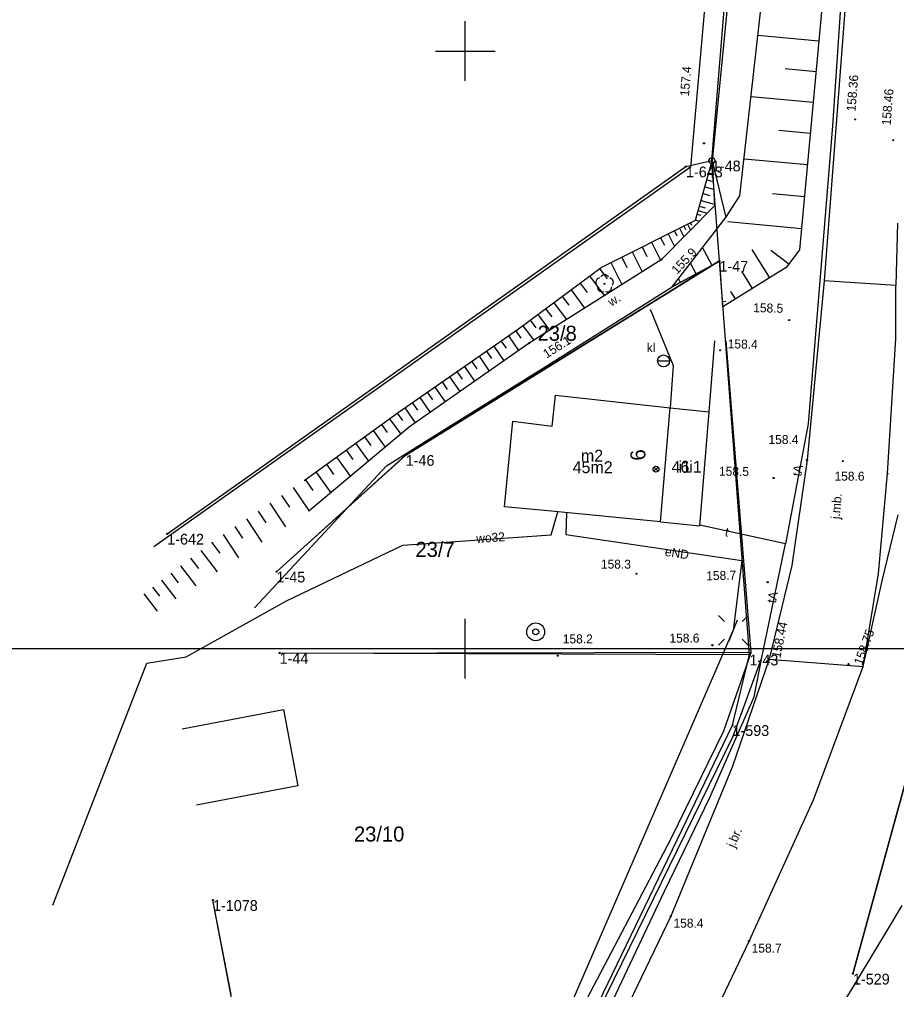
# Model space of a CAD drawing. Extents: x 5598798 to 5599616, y 5661498 to 5662453.
# Drawn here: x 5599112.7 to 5599186.1, y 5661721.5 to 5661802.6 of the extents above; entities that cross this region are included whole.
import ezdxf

# ---------------------------------------------------------------- set-up
doc = ezdxf.new("R2010")
doc.units = 0
for name, color, linetype in [('BUBZ_L_1', 7, 'Continuous'), ('BUIB_L_1', 7, 'Continuous'), ('Dzialki', 7, 'Continuous'), ('EADTD_T_0', 7, 'Continuous'), ('EAPADR_T_0', 7, 'Continuous'), ('EGBB_E_T_0', 7, 'Continuous'), ('EGBB_E_T_1', 7, 'Continuous'), ('EGBB_L_0', 7, 'Continuous'), ('Kontury', 7, 'Continuous'), ('KTJZ_E_T_0', 7, 'Continuous'), ('KTJZ_L_0', 7, 'Continuous'), ('KTOK_L_4', 7, 'Continuous'), ('Numery_dzialek', 7, 'Continuous'), ('Numery_punktow', 7, 'Continuous'), ('OBOP_T_1', 7, 'Continuous'), ('Podzial_sekcyjny_krzyze', 7, 'Continuous'), ('Podzial_sekcyjny_podstawowy', 7, 'Continuous'), ('PTRW_E_T_0', 7, 'Continuous'), ('PTRW_L_1', 7, 'Continuous'), ('Punkty', 7, 'Continuous'), ('RTPW_T_0', 7, 'Continuous'), ('RTPW_T_1', 7, 'Continuous'), ('SUPE_E_T_3', 7, 'Continuous'), ('SUPE_L_3', 7, 'Continuous'), ('SUPT_E_T_0', 7, 'Continuous'), ('SUPT_L_0', 7, 'Continuous'), ('SUPW_E_T_0', 7, 'Continuous'), ('SUPW_L_0', 7, 'Continuous'), ('SUSM_L_4', 7, 'Continuous'), ('SUSM_T_0', 7, 'Continuous'), ('SUUK_E_T_1', 7, 'Continuous'), ('SUUK_T_1', 7, 'Continuous'), ('SUUW_T_1', 7, 'Continuous'), ('Uzytki', 7, 'Continuous')]:
    doc.layers.add(name, color=color, linetype=linetype)

# ---------------------------------------------------------------- blocks, each defined once
blk = doc.blocks.new('GRT')
blk.add_circle((0, 0), 0.25)
blk = doc.blocks.new('GRO')
blk.add_circle((0, 0), 0.045)
blk = doc.blocks.new('1_PADR')
for p, q in [((-0.17675, -0.17675), (0.17675, 0.17675)), ((0.17675, -0.17675), (-0.17675, 0.17675))]:
    blk.add_line(p, q)
blk.add_circle((0, 0), 0.25)
blk = doc.blocks.new('2_OBOP02_01')
blk.add_circle((0, 0), 0.045)
for centre, start, end in [((-0.356659, 0.115892), 102.144465, 221.860023), ((0, 0.375056), 30.140124, 149.859876), ((0.356659, 0.115892), 318.139977, 77.855535), ((-0.220404, -0.303384), 174.148182, 293.854228), ((0.220404, -0.303384), 246.145772, 5.851818)]:
    blk.add_arc(centre, 0.375, start, end)
blk = doc.blocks.new('2_RTPW02')
blk.add_circle((0, 0), 0.045)
blk = doc.blocks.new('2_RTPW01')
blk.add_circle((0, 0), 0.045)
blk = doc.blocks.new('4_SUSM01_01')
for p, q in [((-0.74249, 0.74249), (-1.23746, 1.23746)), ((0.74249, 0.74249), (1.23746, 1.23746)), ((-0.74249, -0.74249), (-1.23746, -1.23746)), ((0.74249, -0.74249), (1.23746, -1.23746))]:
    blk.add_line(p, q)
blk = doc.blocks.new('4_SUUS07')
blk.add_line((-0.5, 0), (0.5, 0))
blk.add_circle((0, 0), 0.5)
blk = doc.blocks.new('4_SUUS13')
for radius in [0.75, 0.25]:
    blk.add_circle((0, 0), radius)

msp = doc.modelspace()

# ---------------------------------------------------------------- linework, layer by layer
at = {"layer": 'BUBZ_L_1'}
for p, q in [((5599172.972858, 5661787.874103), (5599177.287427, 5661826.126371)), ((5599181.907869, 5661825.924682), (5599177.972049, 5661783.365144)), ((5599179.586211, 5661800.819701), (5599174.486221, 5661801.291337)), ((5599179.350392, 5661798.269706), (5599176.774764, 5661798.507895)), ((5599179.112203, 5661795.694078), (5599173.909164, 5661796.175244)), ((5599178.87162, 5661793.092558), (5599176.243949, 5661793.33556)), ((5599169.251478, 5661785.835598), (5599170.668051, 5661790.79835)), ((5599170.545984, 5661790.370707), (5599170.689119, 5661790.32985)), ((5599170.668051, 5661790.79835), (5599170.837218, 5661787.036514)), ((5599178.628618, 5661790.464887), (5599173.320447, 5661790.955776)), ((5599170.381954, 5661789.796053), (5599170.717429, 5661789.700294)), ((5599170.053894, 5661788.646745), (5599170.774051, 5661788.441183)), ((5599170.217924, 5661789.221399), (5599170.74574, 5661789.070739)), ((5599169.889865, 5661788.072091), (5599170.464518, 5661787.908062)), ((5599171.785968, 5661786.07152), (5599172.972858, 5661787.874103)), ((5599178.383174, 5661787.810802), (5599175.702409, 5661788.058713)), ((5599170.837218, 5661787.036514), (5599166.393744, 5661782.537358)), ((5599169.588917, 5661787.017767), (5599170.068587, 5661786.88085)), ((5599169.725835, 5661787.497437), (5599170.830672, 5661787.182072)), ((5599169.397064, 5661786.345639), (5599169.692651, 5661786.261267)), ((5599169.481437, 5661786.641225), (5599170.234521, 5661786.426264)), ((5599161.355952, 5661781.887835), (5599169.251478, 5661785.835598)), ((5599167.305753, 5661780.267008), (5599171.785968, 5661786.07152)), ((5599168.284655, 5661785.352186), (5599168.434068, 5661785.05336)), ((5599168.583481, 5661785.501599), (5599168.831466, 5661785.005628)), ((5599168.831466, 5661785.625592), (5599168.934364, 5661785.419797)), ((5599169.259825, 5661785.864843), (5599169.587635, 5661785.771272)), ((5599178.135262, 5661785.130036), (5599171.955612, 5661785.701518)), ((5599166.967786, 5661784.693752), (5599167.490655, 5661783.648014)), ((5599167.490655, 5661784.955186), (5599167.70761, 5661784.521275)), ((5599167.924566, 5661785.172142), (5599168.284655, 5661784.451964)), ((5599165.587022, 5661784.00337), (5599166.337723, 5661782.501969)), ((5599166.337723, 5661784.37872), (5599166.652754, 5661783.748657)), ((5599163.96489, 5661783.192304), (5599164.796772, 5661781.528539)), ((5599164.796772, 5661783.608245), (5599165.191897, 5661782.817995)), ((5599170.646401, 5661782.058737), (5599169.843769, 5661783.55523)), ((5599175.466879, 5661781.025519), (5599174.008123, 5661783.377679)), ((5599177.05916, 5661782.160799), (5599175.556752, 5661783.299618)), ((5599177.972049, 5661783.365144), (5599176.847765, 5661781.881913)), ((5599166.393744, 5661782.537358), (5599155.337263, 5661775.552894)), ((5599162.167338, 5661782.293528), (5599163.089181, 5661780.44984)), ((5599163.089181, 5661782.75445), (5599163.527036, 5661781.878741)), ((5599171.29896, 5661782.408732), (5599167.305753, 5661780.267008)), ((5599169.325564, 5661781.350317), (5599168.840279, 5661782.255121)), ((5599171.55378, 5661778.598705), (5599171.29896, 5661782.408732)), ((5599154.45566, 5661776.745791), (5599161.355952, 5661781.887835)), ((5599161.228109, 5661781.792568), (5599161.86543, 5661780.937324)), ((5599176.847765, 5661781.881913), (5599171.55378, 5661778.598705)), ((5599174.035488, 5661780.137803), (5599173.147772, 5661781.569194)), ((5599159.610023, 5661780.586782), (5599160.201506, 5661779.79305)), ((5599160.403755, 5661781.178265), (5599161.63236, 5661779.529555)), ((5599168.004727, 5661780.641896), (5599167.83679, 5661780.955012)), ((5599158.845776, 5661780.017271), (5599159.984797, 5661778.488777)), ((5599172.604096, 5661779.250087), (5599172.212551, 5661779.881431)), ((5599157.401397, 5661778.940931), (5599158.457367, 5661777.523888)), ((5599158.109919, 5661779.468916), (5599158.658274, 5661778.733059)), ((5599171.523857, 5661779.046116), (5599171.792795, 5661779.064103)), ((5599156.719195, 5661778.432559), (5599157.227567, 5661777.750358)), ((5599155.429876, 5661777.471769), (5599155.90118, 5661776.83931)), ((5599156.062335, 5661777.943073), (5599157.041309, 5661776.629353)), ((5599144.370619, 5661769.745976), (5599154.45566, 5661776.745791)), ((5599154.220347, 5661776.582465), (5599154.643403, 5661775.972943)), ((5599154.820912, 5661777.017973), (5599155.728503, 5661775.800043)), ((5599155.337263, 5661775.552894), (5599145.33164, 5661768.552295)), ((5599152.997857, 5661775.73396), (5599153.422509, 5661775.12214)), ((5599153.609677, 5661776.158612), (5599154.457384, 5661774.937272)), ((5599151.770756, 5661774.882255), (5599152.197009, 5661774.268127)), ((5599152.384884, 5661775.308508), (5599153.235787, 5661774.082562)), ((5599150.539026, 5661774.027337), (5599150.966887, 5661773.410893)), ((5599151.155471, 5661774.455198), (5599152.009583, 5661773.224628)), ((5599149.302651, 5661773.169195), (5599149.732126, 5661772.550426)), ((5599149.921421, 5661773.59867), (5599150.778755, 5661772.363459)), ((5599148.061613, 5661772.307817), (5599148.492707, 5661771.686714)), ((5599148.682716, 5661772.738911), (5599149.543284, 5661771.499041)), ((5599147.439339, 5661771.87591), (5599148.303153, 5661770.631363)), ((5599146.191273, 5661771.009654), (5599147.058345, 5661769.760413)), ((5599146.815894, 5661771.443189), (5599147.248614, 5661770.819744)), ((5599144.9385, 5661770.14013), (5599145.808842, 5661768.886177)), ((5599145.565476, 5661770.575301), (5599145.999829, 5661769.949504)), ((5599136.508267, 5661764.07314), (5599144.370619, 5661769.745976)), ((5599143.657053, 5661769.231125), (5599144.59343, 5661767.93334)), ((5599144.305946, 5661769.699313), (5599144.757078, 5661769.074059)), ((5599145.33164, 5661768.552295), (5599136.917985, 5661761.497837)), ((5599142.983629, 5661768.745236), (5599143.469517, 5661768.071811)), ((5599141.559438, 5661767.717655), (5599142.08276, 5661766.992349)), ((5599142.284745, 5661768.240978), (5599143.293261, 5661766.843209)), ((5599140.80671, 5661767.174548), (5599141.892925, 5661765.669092)), ((5599139.214805, 5661766.025958), (5599140.384704, 5661764.404519)), ((5599140.025525, 5661766.610908), (5599140.589165, 5661765.829722)), ((5599138.373435, 5661765.418894), (5599138.9805, 5661764.577524)), ((5599137.500257, 5661764.788879), (5599138.760287, 5661763.042521)), ((5599135.610704, 5661763.474764), (5599136.92483, 5661761.503576)), ((5599136.594066, 5661764.135045), (5599137.2479, 5661763.228855)), ((5599134.62642, 5661762.818575), (5599135.28261, 5661761.834291)), ((5599133.643864, 5661762.163537), (5599134.953939, 5661760.198424)), ((5599132.663032, 5661761.509649), (5599133.31692, 5661760.528817)), ((5599130.706528, 5661760.205314), (5599131.358123, 5661759.227921)), ((5599131.683921, 5661760.856909), (5599132.989402, 5661758.898687)), ((5599129.730851, 5661759.554862), (5599131.031754, 5661757.603507)), ((5599128.768573, 5661758.896685), (5599129.475016, 5661757.968819)), ((5599127.872092, 5661758.214137), (5599129.237188, 5661756.421175)), ((5599126.170716, 5661756.918771), (5599127.443378, 5661755.247215)), ((5599127.006494, 5661757.555102), (5599127.665529, 5661756.689505)), ((5599125.363731, 5661756.304362), (5599125.97814, 5661755.497376)), ((5599124.584545, 5661755.711119), (5599125.771032, 5661754.152748)), ((5599123.105778, 5661754.585239), (5599124.211925, 5661753.13239)), ((5599123.832203, 5661755.138312), (5599124.405009, 5661754.38597))]:
    msp.add_line(p, q, dxfattribs=at)
at = {"layer": 'BUIB_L_1'}
for p, q in [((5599156.672887, 5661773.572303), (5599167.305753, 5661780.267008)), ((5599165.47744, 5661778.394591), (5599167.395319, 5661773.685943)), ((5599170.39, 5661769.8), (5599170.880141, 5661775.74608)), ((5599147.004971, 5661767.559842), (5599156.672887, 5661773.572303)), ((5599167.395319, 5661773.685943), (5599167.15, 5661770.15)), ((5599143.395155, 5661765.276761), (5599147.004971, 5661767.559842)), ((5599132.359601, 5661753.410474), (5599143.395155, 5661765.276761))]:
    msp.add_line(p, q, dxfattribs=at)
at = {"layer": 'Dzialki'}
for p, q in [((5599170.63, 5661790.83), (5599180.64, 5661913.54)), ((5599125.06, 5661759.6), (5599168.46, 5661790.33)), ((5599168.46, 5661790.33), (5599170.63, 5661790.83)), ((5599171.26, 5661782.44), (5599170.63, 5661790.83)), ((5599171.26, 5661782.44), (5599145.01, 5661766.19)), ((5599173.78, 5661749.49), (5599171.26, 5661782.44)), ((5599145.01, 5661766.19), (5599134.2, 5661756.43)), ((5599191.7, 5661756.68), (5599182.43, 5661722.79)), ((5599134.46, 5661749.63), (5599173.78, 5661749.49)), ((5599172.35, 5661743.59), (5599173.78, 5661749.49)), ((5599148.41, 5661693.96), (5599172.35, 5661743.59)), ((5599132.54, 5661709.86), (5599128.89, 5661728.95))]:
    msp.add_line(p, q, dxfattribs=at)
at = {"layer": 'EGBB_L_0'}
for p, q in [((5599157.26, 5661768.6), (5599157.56, 5661771.19)), ((5599157.56, 5661771.19), (5599167.15, 5661770.15)), ((5599166.33, 5661760.6), (5599167.15, 5661770.15)), ((5599167.15, 5661770.15), (5599170.39, 5661769.8)), ((5599169.61, 5661760.28), (5599170.39, 5661769.8)), ((5599153.29, 5661761.86), (5599153.99, 5661769.03)), ((5599153.99, 5661769.03), (5599157.26, 5661768.6)), ((5599156.62, 5661761.54), (5599153.29, 5661761.86)), ((5599166.33, 5661760.6), (5599156.62, 5661761.54)), ((5599166.33, 5661760.6), (5599169.61, 5661760.28)), ((5599126.310272, 5661743.289596), (5599134.779895, 5661744.901054)), ((5599134.779895, 5661744.901054), (5599135.993123, 5661738.516793)), ((5599135.993123, 5661738.516793), (5599127.523577, 5661736.905251)), ((5599130.402266, 5661721.050548), (5599128.89, 5661728.95))]:
    msp.add_line(p, q, dxfattribs=at)
at = {"layer": 'Kontury'}
for p, q in [((5599171.26, 5661782.44), (5599145.02, 5661766.19)), ((5599173.78, 5661749.49), (5599171.26, 5661782.44)), ((5599145.02, 5661766.19), (5599134.2, 5661756.43)), ((5599182.43, 5661722.79), (5599191.7, 5661756.68)), ((5599172.35, 5661743.59), (5599173.78, 5661749.49)), ((5599148.41, 5661693.96), (5599172.35, 5661743.59))]:
    msp.add_line(p, q, dxfattribs=at)
at = {"layer": 'KTJZ_L_0'}
for p, q in [((5599182.17, 5661808.73), (5599180.02, 5661780.78)), ((5599186.15, 5661785.6), (5599186.02, 5661780.39)), ((5599180.02, 5661780.78), (5599178.59, 5661765.78)), ((5599186.02, 5661780.39), (5599180.02, 5661780.78)), ((5599186.01, 5661775.95), (5599186.02, 5661780.39)), ((5599185.32, 5661764.64), (5599186.01, 5661775.95)), ((5599178.59, 5661765.78), (5599177.31, 5661756.94)), ((5599184.57, 5661756.28), (5599185.32, 5661764.64)), ((5599184.89, 5661755.66), (5599186.21, 5661761.2)), ((5599177.31, 5661756.94), (5599175.43, 5661749.12)), ((5599183.28, 5661748.5), (5599184.57, 5661756.28)), ((5599183.28, 5661748.5), (5599184.89, 5661755.66)), ((5599175.43, 5661749.12), (5599172.33, 5661740.08)), ((5599175.43, 5661749.12), (5599183.28, 5661748.5)), ((5599179.12, 5661737.33), (5599183.28, 5661748.5)), ((5599172.33, 5661740.08), (5599167.19, 5661727.62)), ((5599173.74, 5661725.53), (5599179.12, 5661737.33)), ((5599167.19, 5661727.62), (5599161.82, 5661716.42)), ((5599161.53, 5661699.74), (5599173.74, 5661725.53))]:
    msp.add_line(p, q, dxfattribs=at)
at = {"layer": 'KTOK_L_4'}
for p, q in [((5599171.05222, 5661814.997676), (5599168.830027, 5661790.290817)), ((5599168.830027, 5661790.290817), (5599123.947757, 5661758.517027)), ((5599167.305753, 5661780.267008), (5599171.29896, 5661782.408732)), ((5599173.915232, 5661749.681447), (5599171.818499, 5661775.744599)), ((5599173.915232, 5661749.681447), (5599134.507237, 5661749.597468)), ((5599171.624053, 5661743.128419), (5599173.915232, 5661749.681447)), ((5599167.170567, 5661734.000977), (5599171.624053, 5661743.128419)), ((5599156.768812, 5661714.174973), (5599167.170567, 5661734.000977))]:
    msp.add_line(p, q, dxfattribs=at)
at = {"layer": 'Podzial_sekcyjny_krzyze'}
for p, q in [((5599150, 5661797.5), (5599150, 5661802.5)), ((5599147.5, 5661800), (5599152.5, 5661800)), ((5599150, 5661747.5), (5599150, 5661752.5)), ((5599147.5, 5661750), (5599152.5, 5661750))]:
    msp.add_line(p, q, dxfattribs=at)
at = {"layer": 'Podzial_sekcyjny_podstawowy'}
msp.add_line((5598800, 5661750), (5599200, 5661750), dxfattribs=at)
at = {"layer": 'PTRW_L_1'}
for p, q in [((5599175.395835, 5661839.501206), (5599170.668051, 5661790.79835)), ((5599172.972858, 5661787.874103), (5599177.287427, 5661826.126371)), ((5599170.668051, 5661790.79835), (5599170.837218, 5661787.036514)), ((5599170.668051, 5661790.79835), (5599171.785968, 5661786.07152)), ((5599171.785968, 5661786.07152), (5599172.972858, 5661787.874103)), ((5599170.837218, 5661787.036514), (5599166.393744, 5661782.537358)), ((5599167.305753, 5661780.267008), (5599171.785968, 5661786.07152)), ((5599166.393744, 5661782.537358), (5599155.337263, 5661775.552894)), ((5599156.672887, 5661773.572303), (5599167.305753, 5661780.267008)), ((5599155.337263, 5661775.552894), (5599145.33164, 5661768.552295)), ((5599147.004971, 5661767.559842), (5599156.672887, 5661773.572303)), ((5599145.33164, 5661768.552295), (5599136.917985, 5661761.497837)), ((5599143.395155, 5661765.276761), (5599147.004971, 5661767.559842)), ((5599132.359601, 5661753.410474), (5599143.395155, 5661765.276761))]:
    msp.add_line(p, q, dxfattribs=at)
at = {"layer": 'SUPE_L_3'}
for p, q in [((5599158.466851, 5661761.361211), (5599158.406534, 5661759.543553)), ((5599158.406534, 5661759.543553), (5599173.129134, 5661757.374253)), ((5599173.129134, 5661757.374253), (5599172.421291, 5661751.519683)), ((5599158.332094, 5661719.064332), (5599172.421291, 5661751.519683))]:
    msp.add_line(p, q, dxfattribs=at)
at = {"layer": 'SUPT_L_0'}
for p, q in [((5599183.629748, 5661836.324248), (5599180.716187, 5661793.727998)), ((5599180.716187, 5661793.727998), (5599178.691605, 5661768.800266)), ((5599178.691605, 5661768.800266), (5599176.789007, 5661758.752312)), ((5599176.789007, 5661758.752312), (5599169.614497, 5661760.33489)), ((5599174.81391, 5661749.25297), (5599176.789007, 5661758.752312)), ((5599172.422232, 5661742.67554), (5599174.81391, 5661749.25297)), ((5599174.1585, 5661745.956529), (5599174.81391, 5661749.25297)), ((5599170.447801, 5661737.548272), (5599174.1585, 5661745.956529)), ((5599157.421027, 5661712.050333), (5599172.422232, 5661742.67554)), ((5599166.67415, 5661729.708853), (5599170.447801, 5661737.548272)), ((5599155.313425, 5661705.739483), (5599166.67415, 5661729.708853))]:
    msp.add_line(p, q, dxfattribs=at)
at = {"layer": 'SUPW_L_0'}
for p, q in [((5599157.172459, 5661759.517034), (5599157.74163, 5661761.431418)), ((5599157.172459, 5661759.517034), (5599157.74163, 5661761.431418)), ((5599144.786248, 5661758.655245), (5599157.172459, 5661759.517034)), ((5599144.786248, 5661758.655245), (5599157.172459, 5661759.517034)), ((5599135.02765, 5661753.991359), (5599144.786248, 5661758.655245)), ((5599135.02765, 5661753.991359), (5599144.786248, 5661758.655245)), ((5599126.650349, 5661749.298839), (5599135.02765, 5661753.991359)), ((5599115.497332, 5661728.515688), (5599123.360738, 5661748.77386)), ((5599123.360738, 5661748.77386), (5599126.650349, 5661749.298839)), ((5599186.52, 5661728.5), (5599185.42, 5661726.64)), ((5599185.42, 5661726.64), (5599181.47, 5661720.11))]:
    msp.add_line(p, q, dxfattribs=at)
at = {"layer": 'SUSM_L_4'}
msp.add_line((5599172.071084, 5661750.641314), (5599172.771498, 5661752.398053), dxfattribs=at)
at = {"layer": 'Uzytki'}
for p, q in [((5599170.63, 5661790.83), (5599180.64, 5661913.54)), ((5599171.26, 5661782.44), (5599170.63, 5661790.83)), ((5599145.02, 5661766.19), (5599171.26, 5661782.44)), ((5599173.78, 5661749.49), (5599171.26, 5661782.44)), ((5599134.2, 5661756.43), (5599145.02, 5661766.19)), ((5599191.7, 5661756.68), (5599182.43, 5661722.79)), ((5599172.35, 5661743.59), (5599173.78, 5661749.49)), ((5599148.41, 5661693.96), (5599172.35, 5661743.59))]:
    msp.add_line(p, q, dxfattribs=at)

# ---------------------------------------------------------------- block references
at = {"layer": 'EAPADR_T_0'}
msp.add_blockref('1_PADR', (5599165.955042, 5661765.013753), dxfattribs=at)
at = {"layer": 'OBOP_T_1'}
msp.add_blockref('2_OBOP02_01', (5599161.654522, 5661780.527681), dxfattribs=at)
at = {"layer": 'Punkty'}
for name, p in [('GRT', (5599170.63, 5661790.83)), ('GRO', (5599168.46, 5661790.33)), ('GRO', (5599171.26, 5661782.44)), ('GRO', (5599145.01, 5661766.19)), ('GRO', (5599125.06, 5661759.6)), ('GRO', (5599134.2, 5661756.43)), ('GRO', (5599134.46, 5661749.63)), ('GRO', (5599173.78, 5661749.49)), ('GRO', (5599172.35, 5661743.59)), ('GRO', (5599128.89, 5661728.95)), ('GRO', (5599182.43, 5661722.79))]:
    msp.add_blockref(name, p, dxfattribs=at)
at = {"layer": 'RTPW_T_0'}
for p in [(5599169.97055, 5661792.273745), (5599166.393744, 5661782.537358), (5599177.099891, 5661777.489612), (5599155.337263, 5661775.552894), (5599171.327532, 5661774.960058), (5599175.803126, 5661764.272515), (5599164.330433, 5661756.261249), (5599175.300909, 5661755.557002), (5599170.66862, 5661750.284776), (5599157.732469, 5661749.404995)]:
    msp.add_blockref('2_RTPW01', p, dxfattribs=at)
at = {"layer": 'RTPW_T_0', "rotation": -3.0000000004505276e-06}
for p in [(5599178.59, 5661765.78), (5599181.59, 5661765.69), (5599185.32, 5661764.64), (5599167.19, 5661727.62), (5599173.74, 5661725.53)]:
    msp.add_blockref('2_RTPW01', p, dxfattribs=at)
at = {"layer": 'RTPW_T_1'}
for p in [(5599182.622328, 5661794.276474), (5599185.798785, 5661792.533155), (5599175.231619, 5661748.922304), (5599182.059696, 5661748.707319)]:
    msp.add_blockref('2_RTPW02', p, dxfattribs=at)
at = {"layer": 'SUSM_T_0'}
msp.add_blockref('4_SUSM01_01', (5599172.421291, 5661751.519683), dxfattribs=at)
at = {"layer": 'SUUK_T_1'}
msp.add_blockref('4_SUUS07', (5599166.586266, 5661774.067744), dxfattribs=at)
at = {"layer": 'SUUW_T_1'}
msp.add_blockref('4_SUUS13', (5599155.890364, 5661751.396245), dxfattribs=at)

# ---------------------------------------------------------------- texts
at = {"layer": 'EADTD_T_0'}
msp.add_text('6', height=1.25, rotation=95.204959, dxfattribs=at).set_placement((5599165.10557, 5661765.787044))
at = {"layer": 'EGBB_E_T_0'}
for s, p in [('m2', (5599159.675838, 5661765.638571)), ('i1', (5599167.837271, 5661764.7075))]:
    msp.add_text(s, height=1, dxfattribs=at).set_placement(p)
at = {"layer": 'EGBB_E_T_1'}
for s, p in [('45m2', (5599158.984114, 5661764.675844)), ('46i1', (5599167.2568, 5661764.7075))]:
    msp.add_text(s, height=1, dxfattribs=at).set_placement(p)
at = {"layer": 'KTJZ_E_T_0'}
for s, rotation, p in [('j.mb.', 85, (5599181.321315, 5661760.807525)), ('j.br.', 66.999993, (5599172.526417, 5661733.282248))]:
    msp.add_text(s, height=0.75, rotation=rotation, dxfattribs=at).set_placement(p)
at = {"layer": 'Numery_dzialek'}
for s, p in [('23/8', (5599156.04642, 5661775.754003)), ('23/7', (5599145.829221, 5661757.667019)), ('23/10', (5599140.683784, 5661733.853365))]:
    msp.add_text(s, height=1.26, dxfattribs=at).set_placement(p)
at = {"layer": 'Numery_punktow'}
for s, p in [('1-643', (5599168.46, 5661789.43)), ('1-48', (5599170.63, 5661789.93)), ('1-47', (5599171.26, 5661781.54)), ('1-46', (5599145.01, 5661765.29)), ('1-642', (5599125.06, 5661758.7)), ('1-45', (5599134.2, 5661755.53)), ('1-44', (5599134.46, 5661748.73)), ('1-43', (5599173.78, 5661748.59)), ('1-593', (5599172.35, 5661742.69)), ('1-1078', (5599128.89, 5661728.05)), ('1-529', (5599182.43, 5661721.89))]:
    msp.add_text(s, height=0.9, dxfattribs=at).set_placement(p)
at = {"layer": 'PTRW_E_T_0'}
msp.add_text('w.', height=0.75, rotation=33.206567, dxfattribs=at).set_placement((5599162.235603, 5661778.593321))
at = {"layer": 'RTPW_T_0'}
for s, rotation, p in [('157.4', 85.392709, (5599168.709919, 5661796.188333)), ('155.9', 46.771459, (5599167.716012, 5661781.26778)), ('158.5', 358.567904, (5599174.081014, 5661778.153102)), ('156.1', 32.048631, (5599156.799912, 5661774.257444)), ('158.4', 358.919076, (5599171.949554, 5661775.125931)), ('158.5', 359.138474, (5599171.220319, 5661764.472412)), ('158.3', 359.795373, (5599161.34473, 5661756.692517)), ('158.7', 1.374825, (5599170.167417, 5661755.712152)), ('158.6', 0.326473, (5599167.08163, 5661750.492117))]:
    msp.add_text(s, height=0.75, rotation=rotation, dxfattribs=at).set_placement(p)
for s, p in [('158.4', (5599175.365154, 5661767.113834)), ('158.6', (5599180.890141, 5661764.048878)), ('158.2', (5599158.155699, 5661750.429183)), ('158.4', (5599167.42, 5661726.65)), ('158.7', (5599173.96, 5661724.56))]:
    msp.add_text(s, height=0.75, dxfattribs=at).set_placement(p)
at = {"layer": 'RTPW_T_1'}
for s, rotation, p in [('158.36', 85.426068, (5599182.643062, 5661794.919229)), ('158.46', 85.497812, (5599185.586468, 5661793.753975)), ('158.44', 78.541237, (5599176.353047, 5661749.153847)), ('158.75', 70.042596, (5599183.197409, 5661748.557684))]:
    msp.add_text(s, height=0.75, rotation=rotation, dxfattribs=at).set_placement(p)
at = {"layer": 'SUPE_E_T_3'}
msp.add_text('eND', height=0.75, rotation=351.618071, dxfattribs=at).set_placement((5599166.663852, 5661757.757337))
at = {"layer": 'SUPT_E_T_0'}
for s, rotation, p in [('tA', 79.277886, (5599178.084549, 5661764.363321)), ('t', 347.560699, (5599171.678019, 5661759.417505)), ('tA', 78.254451, (5599175.970175, 5661753.753811))]:
    msp.add_text(s, height=0.75, rotation=rotation, dxfattribs=at).set_placement(p)
at = {"layer": 'SUPW_E_T_0'}
msp.add_text('wo32', height=0.75, rotation=3.980023, dxfattribs=at).set_placement((5599150.943674, 5661758.828688))
at = {"layer": 'SUUK_E_T_1'}
msp.add_text('kl', height=0.75, dxfattribs=at).set_placement((5599165.183175, 5661774.805486))

doc.saveas('drawing.dxf')
